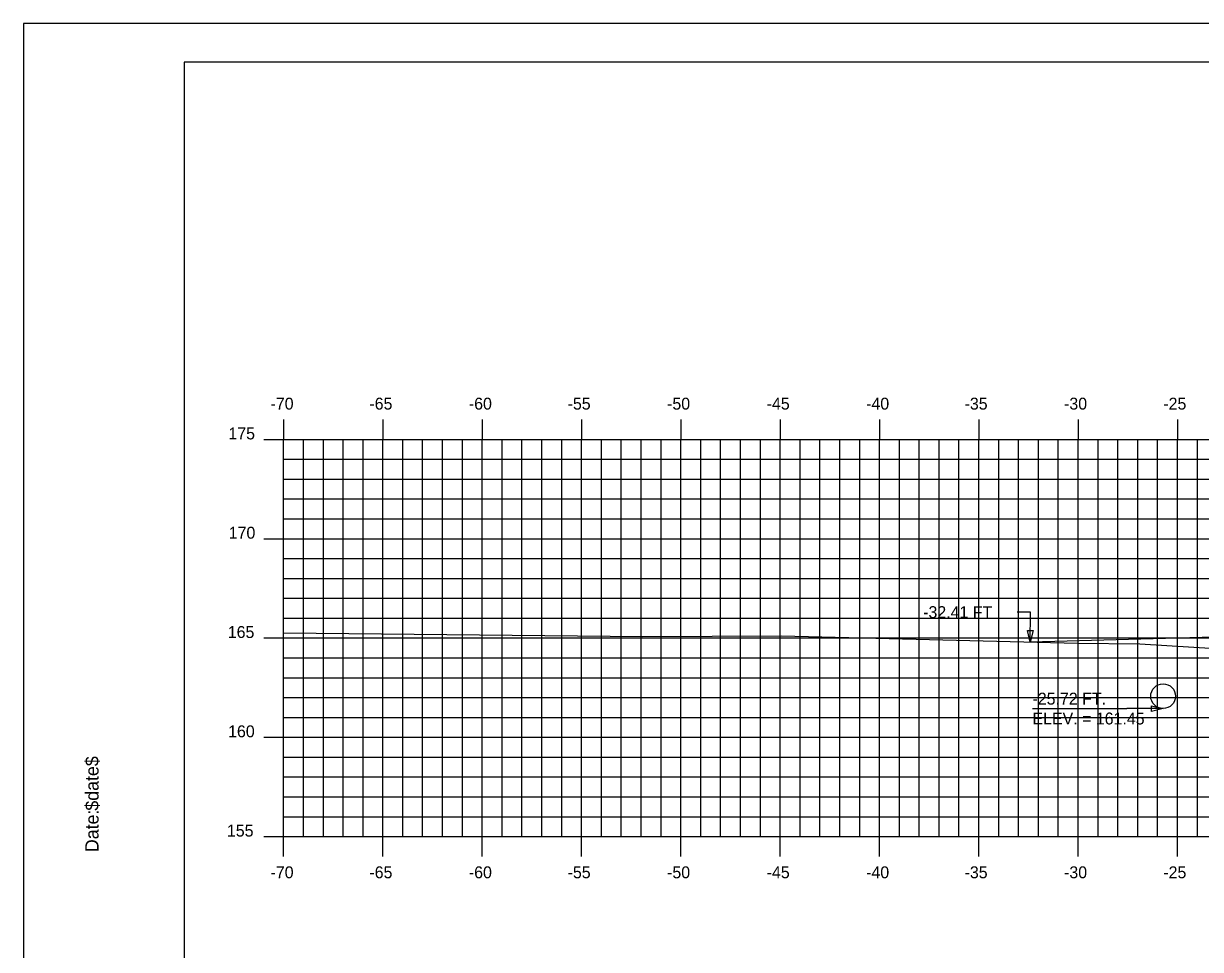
# Model space of a CAD drawing. Extents: x 1142533 to 1142703, y 608981 to 609091.
# Drawn here: x 1142533 to 1142592.2, y 609044.6 to 609091.3 of the extents above; entities that cross this region are included whole.
import ezdxf

# ---------------------------------------------------------------- set-up
doc = ezdxf.new("R2010")
doc.units = 0
for name, color, linetype in [('BORDER', 7, 'Continuous'), ('D_Drainage_Culvert', 7, 'Continuous'), ('D_Roadway_SlopeLines', 7, 'Continuous'), ('D_Text_Standard', 7, 'Continuous'), ('H_V ANNOTATION', 7, 'Continuous'), ('MAJOR', 7, 'Continuous'), ('MINOR', 7, 'Continuous'), ('PLOT BOUNDARY', 7, 'Continuous'), ('S_Roadway_Centerline', 7, 'Continuous')]:
    doc.layers.add(name, color=color, linetype=linetype)

msp = doc.modelspace()

# ---------------------------------------------------------------- linework, layer by layer
at = {"layer": 'BORDER'}
msp.add_lwpolyline([(1142541.054, 608984.335), (1142701.054, 608984.335), (1142701.054, 609089.335), (1142541.054, 609089.335)], close=True, dxfattribs=at)
at = {"layer": 'D_Drainage_Culvert'}
msp.add_circle((1142590.33, 609057.405), 0.625, dxfattribs=at)
at = {"layer": 'D_Roadway_SlopeLines'}
msp.add_line((1142593.711, 609060.391), (1142583.639, 609060.126), dxfattribs=at)
at = {"layer": 'D_Text_Standard'}
msp.add_line((1142583.752, 609056.78), (1142588.51, 609056.78), dxfattribs=at)
for points in [[(1142583.639, 609060.126), (1142583.655, 609061.636), (1142582.975, 609061.636)], [(1142590.33, 609056.78), (1142589.19, 609056.78), (1142588.51, 609056.78)]]:
    msp.add_lwpolyline(points, dxfattribs=at)
for points in [[(1142583.639, 609060.126), (1142583.5, 609060.709), (1142583.791, 609060.706)], [(1142590.33, 609056.78), (1142589.748, 609056.635), (1142589.748, 609056.926)]]:
    msp.add_lwpolyline(points, close=True, dxfattribs=at)
at = {"layer": 'MAJOR'}
for p, q in [((1142546.053, 609071.337), (1142546.053, 609070.335)), ((1142551.053, 609071.337), (1142551.053, 609070.335)), ((1142556.053, 609071.337), (1142556.053, 609070.335)), ((1142561.053, 609071.337), (1142561.053, 609070.335)), ((1142566.053, 609071.337), (1142566.053, 609070.335)), ((1142571.053, 609071.337), (1142571.053, 609070.335)), ((1142576.053, 609071.337), (1142576.053, 609070.335)), ((1142581.053, 609071.337), (1142581.053, 609070.335)), ((1142586.053, 609071.337), (1142586.053, 609070.335)), ((1142591.053, 609071.337), (1142591.053, 609070.335)), ((1142545.051, 609070.335), (1142546.053, 609070.335)), ((1142546.053, 609070.335), (1142686.053, 609070.335)), ((1142546.053, 609050.335), (1142546.053, 609070.335)), ((1142546.053, 609050.335), (1142546.053, 609070.335)), ((1142546.053, 609070.335), (1142686.053, 609070.335)), ((1142551.053, 609050.335), (1142551.053, 609070.335)), ((1142556.053, 609050.335), (1142556.053, 609070.335)), ((1142561.053, 609050.335), (1142561.053, 609070.335)), ((1142566.053, 609050.335), (1142566.053, 609070.335)), ((1142571.053, 609050.335), (1142571.053, 609070.335)), ((1142576.053, 609050.335), (1142576.053, 609070.335)), ((1142581.053, 609050.335), (1142581.053, 609070.335)), ((1142586.053, 609050.335), (1142586.053, 609070.335)), ((1142591.053, 609050.335), (1142591.053, 609070.335)), ((1142545.051, 609065.335), (1142546.053, 609065.335)), ((1142546.053, 609065.335), (1142686.053, 609065.335)), ((1142545.051, 609060.335), (1142546.053, 609060.335)), ((1142546.053, 609060.335), (1142686.053, 609060.335)), ((1142545.051, 609055.335), (1142546.053, 609055.335)), ((1142546.053, 609055.335), (1142686.053, 609055.335)), ((1142545.051, 609050.335), (1142546.053, 609050.335)), ((1142546.053, 609050.335), (1142686.053, 609050.335)), ((1142546.053, 609050.335), (1142686.053, 609050.335)), ((1142546.053, 609049.333), (1142546.053, 609050.335)), ((1142551.053, 609049.333), (1142551.053, 609050.335)), ((1142556.053, 609049.333), (1142556.053, 609050.335)), ((1142561.053, 609049.333), (1142561.053, 609050.335)), ((1142566.053, 609049.333), (1142566.053, 609050.335)), ((1142571.053, 609049.333), (1142571.053, 609050.335)), ((1142576.053, 609049.333), (1142576.053, 609050.335)), ((1142581.053, 609049.333), (1142581.053, 609050.335)), ((1142586.053, 609049.333), (1142586.053, 609050.335)), ((1142591.053, 609049.333), (1142591.053, 609050.335))]:
    msp.add_line(p, q, dxfattribs=at)
at = {"layer": 'MINOR'}
for p, q in [((1142547.053, 609050.335), (1142547.053, 609070.335)), ((1142548.053, 609050.335), (1142548.053, 609070.335)), ((1142549.053, 609050.335), (1142549.053, 609070.335)), ((1142550.053, 609050.335), (1142550.053, 609070.335)), ((1142552.053, 609050.335), (1142552.053, 609070.335)), ((1142553.053, 609050.335), (1142553.053, 609070.335)), ((1142554.053, 609050.335), (1142554.053, 609070.335)), ((1142555.053, 609050.335), (1142555.053, 609070.335)), ((1142557.053, 609050.335), (1142557.053, 609070.335)), ((1142558.053, 609050.335), (1142558.053, 609070.335)), ((1142559.053, 609050.335), (1142559.053, 609070.335)), ((1142560.053, 609050.335), (1142560.053, 609070.335)), ((1142562.053, 609050.335), (1142562.053, 609070.335)), ((1142563.053, 609050.335), (1142563.053, 609070.335)), ((1142564.053, 609050.335), (1142564.053, 609070.335)), ((1142565.053, 609050.335), (1142565.053, 609070.335)), ((1142567.053, 609050.335), (1142567.053, 609070.335)), ((1142568.053, 609050.335), (1142568.053, 609070.335)), ((1142569.053, 609050.335), (1142569.053, 609070.335)), ((1142570.053, 609050.335), (1142570.053, 609070.335)), ((1142572.053, 609050.335), (1142572.053, 609070.335)), ((1142573.053, 609050.335), (1142573.053, 609070.335)), ((1142574.053, 609050.335), (1142574.053, 609070.335)), ((1142575.053, 609050.335), (1142575.053, 609070.335)), ((1142577.053, 609050.335), (1142577.053, 609070.335)), ((1142578.053, 609050.335), (1142578.053, 609070.335)), ((1142579.053, 609050.335), (1142579.053, 609070.335)), ((1142580.053, 609050.335), (1142580.053, 609070.335)), ((1142582.053, 609050.335), (1142582.053, 609070.335)), ((1142583.053, 609050.335), (1142583.053, 609070.335)), ((1142584.053, 609050.335), (1142584.053, 609070.335)), ((1142585.053, 609050.335), (1142585.053, 609070.335)), ((1142587.053, 609050.335), (1142587.053, 609070.335)), ((1142588.053, 609050.335), (1142588.053, 609070.335)), ((1142589.053, 609050.335), (1142589.053, 609070.335)), ((1142590.053, 609050.335), (1142590.053, 609070.335)), ((1142592.053, 609050.335), (1142592.053, 609070.335)), ((1142546.053, 609069.335), (1142686.053, 609069.335)), ((1142546.053, 609069.335), (1142547.055, 609069.335)), ((1142546.053, 609068.335), (1142686.053, 609068.335)), ((1142546.053, 609068.335), (1142547.055, 609068.335)), ((1142546.053, 609067.335), (1142686.053, 609067.335)), ((1142546.053, 609067.335), (1142547.055, 609067.335)), ((1142546.053, 609066.335), (1142686.053, 609066.335)), ((1142546.053, 609066.335), (1142547.055, 609066.335)), ((1142546.053, 609064.335), (1142686.053, 609064.335)), ((1142546.053, 609064.335), (1142547.055, 609064.335)), ((1142546.053, 609063.335), (1142686.053, 609063.335)), ((1142546.053, 609063.335), (1142547.055, 609063.335)), ((1142546.053, 609062.335), (1142686.053, 609062.335)), ((1142546.053, 609062.335), (1142547.055, 609062.335)), ((1142546.053, 609061.335), (1142686.053, 609061.335)), ((1142546.053, 609061.335), (1142547.055, 609061.335)), ((1142546.053, 609059.335), (1142686.053, 609059.335)), ((1142546.053, 609059.335), (1142547.055, 609059.335)), ((1142546.053, 609058.335), (1142686.053, 609058.335)), ((1142546.053, 609058.335), (1142547.055, 609058.335)), ((1142546.053, 609057.335), (1142686.053, 609057.335)), ((1142546.053, 609057.335), (1142547.055, 609057.335)), ((1142546.053, 609056.335), (1142686.053, 609056.335)), ((1142546.053, 609056.335), (1142547.055, 609056.335)), ((1142546.053, 609054.335), (1142686.053, 609054.335)), ((1142546.053, 609054.335), (1142547.055, 609054.335)), ((1142546.053, 609053.335), (1142686.053, 609053.335)), ((1142546.053, 609053.335), (1142547.055, 609053.335)), ((1142546.053, 609052.335), (1142686.053, 609052.335)), ((1142546.053, 609052.335), (1142547.055, 609052.335)), ((1142546.053, 609051.335), (1142686.053, 609051.335)), ((1142546.053, 609051.335), (1142547.055, 609051.335))]:
    msp.add_line(p, q, dxfattribs=at)
at = {"layer": 'PLOT BOUNDARY'}
msp.add_lwpolyline([(1142532.96, 608981.276), (1142702.96, 608981.276), (1142702.96, 609091.276), (1142532.96, 609091.276)], close=True, dxfattribs=at)
at = {"layer": 'S_Roadway_Centerline'}
msp.add_lwpolyline([(1142546.053, 609060.596), (1142564.136, 609060.407), (1142571.113, 609060.438), (1142586.023, 609060.066), (1142589.149, 609060.035), (1142594.057, 609059.733), (1142596.736, 609059.787), (1142597.575, 609059.795), (1142598.896, 609060.234), (1142602.888, 609060.217), (1142602.895, 609060.218), (1142602.929, 609060.219), (1142613.821, 609060.416), (1142618.977, 609060.242), (1142625.024, 609060.106), (1142626.441, 609059.985), (1142628.873, 609059.705), (1142630.597, 609059.311), (1142631.85, 609058.883), (1142634.658, 609059.303), (1142636.46, 609059.594), (1142653.28, 609059.37), (1142667.439, 609059.325), (1142686.053, 609059.248)], dxfattribs=at)

# ---------------------------------------------------------------- texts
at = {"layer": 'BORDER'}
for s, p in [('$date$', (1142536.739, 609051.64)), ('Date:', (1142536.739, 609049.552))]:
    msp.add_text(s, height=0.6696, rotation=90, dxfattribs=at).set_placement(p)
at = {"layer": 'D_Text_Standard'}
for s, p in [('-32.41 FT', (1142578.249, 609061.336)), ('-25.72 FT.', (1142583.752, 609056.98)), ('ELEV. = 161.45', (1142583.752, 609055.98))]:
    msp.add_text(s, height=0.6, dxfattribs=at).set_placement(p)
at = {"layer": 'H_V ANNOTATION'}
for s, p in [('-70', (1142545.395, 609071.835)), ('-65', (1142550.371, 609071.835)), ('-60', (1142555.379, 609071.835)), ('-50', (1142565.358, 609071.835)), ('-40', (1142575.379, 609071.835)), ('-35', (1142580.334, 609071.835)), ('-30', (1142585.342, 609071.835)), ('-25', (1142590.339, 609071.835)), ('-55', (1142560.35, 609071.835)), ('-45', (1142570.371, 609071.835)), ('175', (1142543.274, 609070.335)), ('170', (1142543.29, 609065.335)), ('165', (1142543.242, 609060.335)), ('160', (1142543.258, 609055.335)), ('155', (1142543.199, 609050.335)), ('-70', (1142545.395, 609048.235)), ('-65', (1142550.371, 609048.235)), ('-60', (1142555.379, 609048.235)), ('-55', (1142560.35, 609048.235)), ('-50', (1142565.358, 609048.235)), ('-45', (1142570.371, 609048.235)), ('-40', (1142575.379, 609048.235)), ('-35', (1142580.334, 609048.235)), ('-30', (1142585.342, 609048.235)), ('-25', (1142590.339, 609048.235))]:
    msp.add_text(s, height=0.6, dxfattribs=at).set_placement(p)
at = {"layer": 'MAJOR'}
msp.add_text('-', height=0.006, dxfattribs=at).set_placement((1142546.049, 609050.335))

doc.saveas('drawing.dxf')
